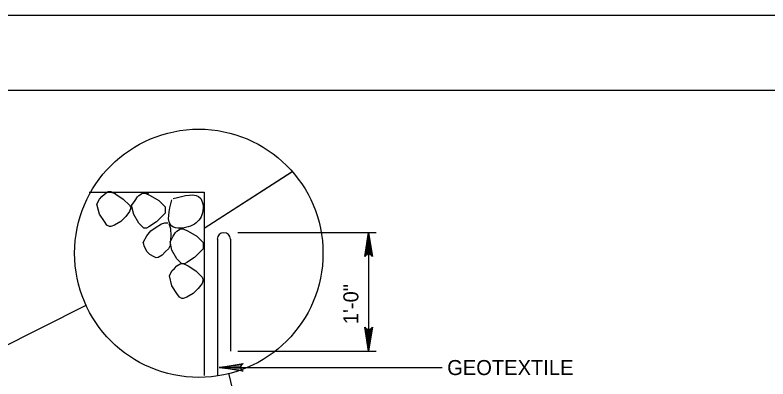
# Model space of a CAD drawing. Extents: x 593 to 1473, y 721 to 1315.
# Drawn here: x 1025.6 to 1175.8, y 1242.7 to 1315.4 of the extents above; entities that cross this region are included whole.
import ezdxf

# ---------------------------------------------------------------- set-up
doc = ezdxf.new("R2010")
doc.units = 0
for name, color, linetype in [('1', 7, 'Continuous'), ('2', 7, 'Continuous'), ('PLT-BNDY', 7, 'Continuous')]:
    doc.layers.add(name, color=color, linetype=linetype)

msp = doc.modelspace()

# ---------------------------------------------------------------- linework, layer by layer
at = {"layer": '1'}
for points in [[(1095.57, 1267.43), (1095.9, 1267.6), (1096.14, 1271.97), (1095.57, 1267.43), (1095.37, 1267.2), (1096.14, 1271.97), (1096.36, 1267.6), (1096.69, 1267.45), (1096.14, 1271.97), (1096.9, 1267.2), (1096.69, 1267.45)], [(1095.57, 1267.43), (1095.9, 1267.6), (1096.14, 1271.97), (1095.57, 1267.43), (1095.37, 1267.2), (1096.14, 1271.97), (1096.36, 1267.6), (1096.69, 1267.45), (1096.14, 1271.97), (1096.9, 1267.2), (1096.69, 1267.45)], [(1096.71, 1252.83), (1096.39, 1252.66), (1096.14, 1248.29), (1096.71, 1252.83), (1096.91, 1253.07), (1096.14, 1248.29), (1095.93, 1252.66), (1095.6, 1252.82), (1096.14, 1248.29), (1095.39, 1253.07), (1095.6, 1252.82)], [(1096.71, 1252.83), (1096.39, 1252.66), (1096.14, 1248.29), (1096.71, 1252.83), (1096.91, 1253.07), (1096.14, 1248.29), (1095.93, 1252.66), (1095.6, 1252.82), (1096.14, 1248.29), (1095.39, 1253.07), (1095.6, 1252.82)], [(1070.84, 1244.47), (1070.68, 1244.8), (1066.3, 1245.04), (1070.84, 1244.47), (1071.08, 1244.27), (1066.3, 1245.04), (1070.67, 1245.26), (1070.83, 1245.58), (1066.3, 1245.04), (1071.08, 1245.8), (1070.83, 1245.58)]]:
    msp.add_lwpolyline(points, dxfattribs=at)
at = {"layer": '2'}
for p, q in [((632.66, 1300.4), (1418.66, 1300.4)), ((1063.36, 1272.82), (1080.89, 1284.18)), ((1070.05, 1271.97), (1097.64, 1271.97)), ((1096.14, 1271.97), (1096.14, 1248.29)), ((952.82, 1213.91), (1039.76, 1257.45)), ((1070.05, 1248.29), (1097.64, 1248.29)), ((1066.3, 1245.04), (1110.81, 1245.04)), ((1068.18, 1243.92), (1073.92, 1220.69))]:
    msp.add_line(p, q, dxfattribs=at)
for points in [[(1063.36, 1272.82), (1080.83, 1284.12)], [(1043.43, 1279.67), (1044.18, 1280.17)], [(1044.18, 1280.17), (1044.43, 1280.17)], [(1044.43, 1280.17), (1044.68, 1280.17)], [(1044.68, 1280.17), (1045.68, 1279.67)], [(1040.38, 1280.02), (1063.36, 1280.02), (1063.36, 1243.42)], [(1041.93, 1277.67), (1042.43, 1278.67)], [(1042.43, 1278.67), (1042.93, 1279.17)], [(1042.93, 1279.17), (1043.43, 1279.67)], [(1045.43, 1279.92), (1044.93, 1279.92)], [(1045.68, 1279.92), (1045.43, 1279.92)], [(1045.68, 1279.67), (1047.18, 1278.67)], [(1047.18, 1278.67), (1048.43, 1277.42)], [(1049.55, 1278.36), (1050.05, 1279.11)], [(1050.05, 1279.11), (1050.3, 1279.36)], [(1050.3, 1279.36), (1051.05, 1279.86)], [(1051.05, 1279.86), (1051.3, 1279.86)], [(1051.3, 1279.86), (1051.55, 1279.86)], [(1051.55, 1279.86), (1052.55, 1279.36)], [(1052.3, 1279.61), (1051.8, 1279.86)], [(1052.55, 1279.36), (1054.3, 1278.36)], [(1042.43, 1275.67), (1041.93, 1277.67)], [(1048.43, 1277.42), (1048.68, 1276.92)], [(1048.8, 1277.36), (1049.55, 1278.36)], [(1049.3, 1275.61), (1048.8, 1277.36)], [(1054.3, 1278.36), (1055.3, 1277.36)], [(1055.3, 1277.36), (1055.55, 1277.11)], [(1055.55, 1277.11), (1055.55, 1276.61)], [(1043.43, 1274.17), (1042.43, 1275.67)], [(1048.43, 1276.17), (1047.68, 1275.17)], [(1048.68, 1276.92), (1048.43, 1276.17)], [(1050.3, 1273.86), (1049.3, 1275.61)], [(1055.55, 1275.86), (1054.55, 1274.86)], [(1055.55, 1276.61), (1055.55, 1275.86)], [(1043.93, 1273.42), (1043.43, 1274.17)], [(1046.68, 1274.17), (1045.43, 1273.42)], [(1047.68, 1275.17), (1046.68, 1274.17)], [(1053.8, 1274.11), (1052.3, 1273.11)], [(1054.55, 1274.86), (1053.8, 1274.11)], [(1044.43, 1273.17), (1043.93, 1273.42)], [(1044.68, 1273.17), (1044.43, 1273.17)], [(1045.43, 1273.42), (1044.68, 1273.17)], [(1051.05, 1273.11), (1050.3, 1273.86)], [(1051.3, 1272.86), (1051.05, 1273.11)], [(1051.8, 1272.86), (1051.3, 1272.86)], [(1052.3, 1273.11), (1051.8, 1272.86)], [(1052.67, 1272.29), (1053.58, 1272.94)], [(1053.58, 1272.94), (1054.82, 1273.7)], [(1054.82, 1273.7), (1055.5, 1273.91)], [(1055.5, 1273.91), (1056.06, 1273.9)], [(1056.28, 1273.78), (1056.59, 1272.77)], [(1056.59, 1272.77), (1056.67, 1271.32)], [(1057.87, 1272.24), (1058.62, 1272.74)], [(1058.62, 1272.74), (1058.87, 1272.74)], [(1058.87, 1272.74), (1059.12, 1272.74)], [(1059.12, 1272.74), (1060.12, 1272.24)], [(1051.17, 1269.97), (1051.87, 1271.3)], [(1051.87, 1271.3), (1052.67, 1272.29)], [(1056.67, 1271.32), (1056.54, 1269.98)], [(1056.58, 1270.22), (1057.12, 1271.24)], [(1057.12, 1271.24), (1057.62, 1271.99)], [(1057.62, 1271.99), (1057.87, 1272.24)], [(1060.12, 1272.24), (1061.87, 1271.24)], [(1061.87, 1271.24), (1062.87, 1270.24)], [(1051.27, 1269.64), (1051.17, 1269.97)], [(1051.38, 1269.3), (1051.27, 1269.64)], [(1056.54, 1269.98), (1056.52, 1269.42)], [(1056.87, 1268.49), (1056.53, 1270.19)], [(1062.87, 1270.24), (1063.12, 1269.99)], [(1063.12, 1269.99), (1063.12, 1269.49)], [(1065.96, 1270.65), (1065.96, 1243.42)], [(1068.55, 1270.65), (1068.55, 1248.29)], [(1051.91, 1268.17), (1051.38, 1269.3)], [(1052.46, 1267.6), (1051.91, 1268.17)], [(1055.61, 1268.21), (1054.92, 1267.44)], [(1056.18, 1268.75), (1055.61, 1268.21)], [(1056.52, 1269.42), (1056.18, 1268.75)], [(1057.87, 1266.74), (1056.87, 1268.49)], [(1063.12, 1268.74), (1062.12, 1267.74)], [(1063.12, 1269.49), (1063.12, 1268.74)], [(1053.35, 1267.13), (1052.46, 1267.6)], [(1053.76, 1266.92), (1053.35, 1267.13)], [(1054.13, 1267.01), (1053.79, 1266.9)], [(1054.92, 1267.44), (1054.13, 1267.01)], [(1058.62, 1265.99), (1057.87, 1266.74)], [(1061.37, 1266.99), (1059.87, 1265.99)], [(1062.12, 1267.74), (1061.37, 1266.99)], [(1057.4, 1264.81), (1057.9, 1265.31)], [(1057.9, 1265.31), (1058.65, 1265.81)], [(1058.87, 1265.74), (1058.62, 1265.99)], [(1058.65, 1265.81), (1058.9, 1265.81)], [(1059.37, 1265.74), (1058.87, 1265.74)], [(1058.9, 1265.81), (1059.15, 1265.81)], [(1059.15, 1265.81), (1060.15, 1265.31)], [(1059.87, 1265.99), (1059.37, 1265.74)], [(1060.15, 1265.31), (1061.65, 1264.31)], [(1056.4, 1263.31), (1056.9, 1264.31)], [(1056.9, 1264.31), (1057.4, 1264.81)], [(1061.65, 1264.31), (1062.9, 1263.06)], [(1056.9, 1261.31), (1056.4, 1263.31)], [(1062.9, 1263.06), (1063.15, 1262.56)], [(1063.15, 1262.56), (1062.9, 1261.81)], [(1057.9, 1259.81), (1056.9, 1261.31)], [(1062.15, 1260.81), (1061.15, 1259.81)], [(1062.9, 1261.81), (1062.15, 1260.81)], [(1058.4, 1259.06), (1057.9, 1259.81)], [(1061.15, 1259.81), (1059.9, 1259.06)], [(1058.9, 1258.81), (1058.4, 1259.06)], [(1059.15, 1258.81), (1058.9, 1258.81)], [(1059.9, 1259.06), (1059.15, 1258.81)]]:
    msp.add_lwpolyline(points, dxfattribs=at)
msp.add_circle((1062.26, 1267.84), 24.78, dxfattribs=at)
msp.add_arc((1067.25, 1270.65), 1.3, 0, 180, dxfattribs=at)
msp.add_spline([(1057.13, 1278.76), (1062.63, 1278.76), (1062.88, 1275.51), (1060.63, 1273.26), (1056.88, 1273.26), (1056.88, 1278.51)], degree=3, dxfattribs=at)
at = {"layer": 'PLT-BNDY'}
msp.add_lwpolyline([(592.66, 1315.4), (1433.66, 1315.4), (1433.66, 721.4), (592.66, 721.4)], close=True, dxfattribs=at)

# ---------------------------------------------------------------- texts
at = {"layer": '2'}
msp.add_text('1\'-0"', height=3, rotation=90, dxfattribs=at).set_placement((1094.1, 1253.69))
msp.add_text('GEOTEXTILE', height=3, dxfattribs=at).set_placement((1111.83, 1243.52))

doc.saveas('drawing.dxf')
